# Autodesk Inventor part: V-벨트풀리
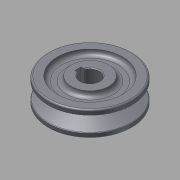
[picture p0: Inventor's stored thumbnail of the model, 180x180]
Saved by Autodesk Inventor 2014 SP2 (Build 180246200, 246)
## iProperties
Created: 2015-12
Part Number: V-벨트풀리
Material: 강철, 연강
Document SubType Name: Modeling
Designer: mdu
Density: 7.86 g/cm^3
Appearance: 강철
CustomPartVersion: 1
Author: mdu
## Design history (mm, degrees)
sketch "주 스케치"
  geometry: L1 (0, 16)-(27, 16); L2 (27, 16)-(27, 12.861); L3 (27, 12.861)-(16, 9.498); L4 (16, 9.498)-(16, 6.502); L5 (16, 6.502)-(27, 3.139); L6 (27, 3.139)-(27, 0); L7 (27, 0)-(0, 0); L8 (25, 12.25)-(25, 3.75); L9 (16, 8)-(25, 8); L10 (27, 12.861)-(27, 3.139); L11 (0, -3)-(0, 18) reference; L12 (0, 0)-(0, 16)
  constraints: 22 end point, 5 perpendicular, 2 collinear, 2 midpoint, 2 point on line, 1 parallel
  dimensions: "d0" = 8.5 distance of L8.start L8.end (= da_Bw); "d1" = 34 deg angle of L3 L5 (= da_Alfa); "d2" = 2 distance between parallel lines of L2 L8 (= da_c); "d6" = 16 distance between parallel lines of L7 L1 (computed from d5, da_ng, da_Sg); "d21" = 50 diameter of L8 L11 (= da_Dw); "d25" = 11 distance between parallel lines of L4 L10 (= da_Hd); "d27" = 8 distance between parallel lines of L7 L9 (= da_Se)
node "벨트 평면"
revolve "본체" stored, may be unused: angle "d7" = 90 deg
revolve "그루브" stored, may be unused: angle "d15" = 90 deg
feature "허브 키홈"
fillet "모깎기3" dims "d28" = 0.5, "d29" = 1, "d30" = 1
sketch "스케치2"
  geometry: C1 r 12 at (0, 0); C2 r 21 at (0, 0); 1 further point
  constraints: 2 centre point, 2 coincident
  dimensions: "d31" = 24 diameter of C1; "d32" = 42 diameter of C2
extrude "돌출1" cut sketch "스케치2" distance "d33" = 3; taper "d34" = 0 deg
fillet "모깎기4" dims "d35" = 3
node "작업 평면2"
chamfer "모따기1" distance "d36" = 0.5; stored, may be unused: second distance "d37" = 2, angle "d38" = 45 deg
body "Solid1"
pattern_linear "그루브 패턴" dims "d18" = 12 (= da_Sg)
mirror "대칭1"
other parameters: "d5" = 8 (= da_Se), "da_Bw" = 8.5 [user parameter; used in 1 equation term], "da_Alfa" = 34 deg [user parameter; used in 1 equation term], "da_c" = 2 [user parameter; used in 1 equation term], "da_Dw" = 50 [user parameter; used in 1 equation term], "da_Hd" = 11 [user parameter; used in 1 equation term], "da_Se" = 8 [user parameter; used in 2 equation terms], "da_Sg" = 12 [user parameter; used in 2 equation terms], "da_r1" = 0 [user parameter], "da_r2" = 0 [user parameter], "d24" = 0, "d26" = 0
